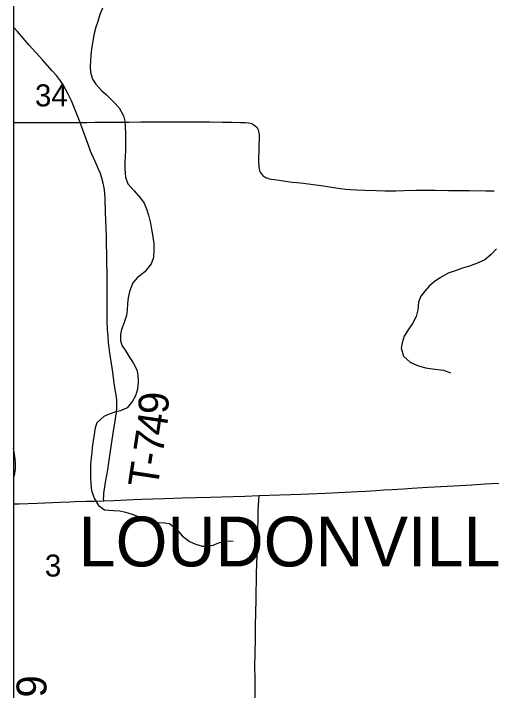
# Model space of a CAD drawing. Extents: x -7.5 to 53.5, y 0 to 22.
# Drawn here: x 2.1 to 3.008, y 16.532 to 17.82 of the extents above; entities that cross this region are included whole.
import ezdxf

# ---------------------------------------------------------------- set-up
doc = ezdxf.new("R2010")
doc.units = 0
for name, color, linetype in [('GM_X_Corporation', 7, 'Continuous'), ('GM_X_Corporation_Text', 7, 'Continuous'), ('GM_X_County_Road', 7, 'Continuous'), ('GM_X_Minor_River', 7, 'Continuous'), ('GM_X_Section_Text', 7, 'Continuous'), ('GM_X_Township_Road', 7, 'Continuous'), ('GM_X_Township_Road_Text', 7, 'Continuous'), ('SH_Data', 7, 'Continuous')]:
    doc.layers.add(name, color=color, linetype=linetype)

msp = doc.modelspace()

# ---------------------------------------------------------------- linework, layer by layer
at = {"layer": 'GM_X_Corporation'}
msp.add_lwpolyline([(4.6087, 14.5302), (4.6021, 15.6139), (4.594, 15.8096), (4.5873, 16.3533), (4.5872, 16.3635), (4.5826, 16.8462), (4.5822, 16.8992), (4.577, 17.1178), (4.5749, 17.2575), (4.5771, 17.6201), (4.5718, 18.1276), (4.5696, 18.2604), (4.5565, 19.1354), (5.0411, 19.1401), (6.0424, 19.1527), (6.0433, 19.1527), (6.5522, 19.1561), (7.544, 19.1455), (8.414, 19.1709), (8.5159, 19.1718), (8.9, 19.1887), (8.9, 20.9), (2.1, 20.9), (2.1, 14.1)], dxfattribs=at)
at = {"layer": 'GM_X_County_Road'}
for points in [[(2.5666, 16.9029), (2.6054, 16.9045), (2.6271, 16.9051), (2.6458, 16.9057), (2.6613, 16.9062), (2.6924, 16.9076), (2.7172, 16.9089), (2.7296, 16.9094), (2.7544, 16.9109), (2.7699, 16.9117), (2.7792, 16.9123), (2.7885, 16.9129), (2.804, 16.9139), (2.8195, 16.9149), (2.8413, 16.9162), (2.8568, 16.9172), (2.8878, 16.9189), (2.925, 16.921), (2.9714, 16.9238), (2.9962, 16.9253), (3.0085, 16.9259), (3.0302, 16.9268), (3.0605, 16.9283)], [(2.2713, 16.8933), (2.2909, 16.8939), (2.3281, 16.8956), (2.3436, 16.8962), (2.3871, 16.8977), (2.4213, 16.8985), (2.4462, 16.8991), (2.4741, 16.8998), (2.5176, 16.9013), (2.5394, 16.9022), (2.5666, 16.9029)], [(2.1, 16.8871), (2.1109, 16.8876), (2.145, 16.8889), (2.1885, 16.8905), (2.2071, 16.8913), (2.2164, 16.8916), (2.2381, 16.8922), (2.2537, 16.8927), (2.2713, 16.8933)]]:
    msp.add_lwpolyline(points, dxfattribs=at)
at = {"layer": 'GM_X_Minor_River'}
for points in [[(2.2688, 17.8302), (2.2642, 17.8184), (2.2604, 17.8051), (2.2566, 17.7945), (2.2528, 17.7797), (2.2509, 17.7679), (2.2486, 17.7569), (2.2466, 17.7417), (2.2463, 17.7303), (2.2459, 17.7193), (2.2462, 17.7087), (2.25, 17.6954), (2.2561, 17.6859), (2.2671, 17.6738), (2.2765, 17.6654), (2.2906, 17.6517), (2.3008, 17.6411), (2.3088, 17.6255), (2.3114, 17.6153), (2.3122, 17.6054), (2.3125, 17.591), (2.3125, 17.5594), (2.3117, 17.5366), (2.3117, 17.5249), (2.3128, 17.5086), (2.3173, 17.496), (2.3291, 17.4831), (2.3412, 17.469), (2.3484, 17.4592), (2.3534, 17.447), (2.3568, 17.4368), (2.3602, 17.4216), (2.3624, 17.4102), (2.3639, 17.3992), (2.3669, 17.3828), (2.3669, 17.3714), (2.3658, 17.3559), (2.3616, 17.3437), (2.3494, 17.3289), (2.335, 17.3175), (2.327, 17.308), (2.3202, 17.2913), (2.3179, 17.2792), (2.3167, 17.2686), (2.3159, 17.2556), (2.3144, 17.2454), (2.3098, 17.2306), (2.3053, 17.2188), (2.303, 17.2093), (2.3033, 17.1976), (2.3064, 17.1877), (2.3132, 17.1778), (2.3211, 17.1649), (2.3276, 17.1554)], [(3.0179, 17.3723), (3.008, 17.362), (2.9959, 17.3514), (2.9833, 17.3457), (2.967, 17.3393), (2.9537, 17.3358), (2.9397, 17.3309), (2.926, 17.326), (2.9097, 17.3169), (2.8994, 17.3097), (2.8899, 17.3017), (2.8815, 17.2922), (2.8743, 17.2827), (2.8698, 17.2713), (2.8682, 17.2565), (2.8652, 17.2436), (2.8583, 17.2303), (2.8503, 17.2186), (2.8424, 17.2064), (2.8389, 17.1939), (2.8366, 17.1833), (2.8412, 17.1684), (2.8541, 17.1567), (2.8677, 17.1506), (2.8833, 17.146), (2.8966, 17.1445), (2.9171, 17.1414), (2.9303, 17.1369)], [(2.3276, 17.1554), (2.3344, 17.1425), (2.3363, 17.1326), (2.3367, 17.1197), (2.3359, 17.1053), (2.3321, 17.0931), (2.326, 17.0829), (2.3157, 17.0703), (2.3032, 17.0643), (2.2926, 17.062), (2.2819, 17.0582), (2.2717, 17.0537), (2.258, 17.0415), (2.2549, 17.032), (2.2511, 17.007), (2.2492, 16.9948), (2.2488, 16.9853), (2.2473, 16.9751), (2.2465, 16.9622), (2.2461, 16.9489), (2.2465, 16.9386), (2.2472, 16.9249), (2.2484, 16.9128), (2.2533, 16.898), (2.2616, 16.8843), (2.273, 16.8759), (2.2897, 16.8744), (2.3018, 16.874), (2.3125, 16.8714), (2.3254, 16.8679), (2.3371, 16.8634), (2.3504, 16.8584), (2.361, 16.8543), (2.3747, 16.852), (2.3868, 16.8512), (2.3967, 16.8501), (2.4104, 16.8387), (2.4206, 16.8265), (2.4342, 16.8155), (2.4449, 16.8113), (2.4585, 16.8071), (2.4684, 16.8067), (2.4794, 16.809), (2.4916, 16.8136), (2.5045, 16.8166), (2.5174, 16.817)], [(2.1, 16.9396), (2.1015, 16.9413), (2.1034, 16.9542), (2.1038, 16.9656), (2.1027, 16.9774), (2.1008, 16.9892), (2.1, 16.9933)]]:
    msp.add_lwpolyline(points, dxfattribs=at)
at = {"layer": 'GM_X_Township_Road'}
for points in [[(2.2265, 17.6131), (2.2218, 17.6254), (2.2099, 17.6541), (2.2033, 17.6682), (2.1989, 17.6764), (2.1943, 17.6845), (2.1893, 17.6923), (2.1857, 17.6973), (2.1817, 17.7021), (2.1735, 17.7114), (2.1549, 17.7324), (2.13, 17.7602), (2.1075, 17.7859), (2.1, 17.7946)], [(2.1, 17.6127), (2.1006, 17.6128), (2.1221, 17.6131), (2.1436, 17.6132), (2.159, 17.6131), (2.1745, 17.6131), (2.1931, 17.6131), (2.2265, 17.6131)], [(2.2265, 17.6131), (2.2331, 17.6131), (2.2393, 17.6131), (2.2548, 17.6134), (2.2983, 17.6136), (2.32, 17.6137), (2.3418, 17.6139), (2.3542, 17.6141), (2.3759, 17.6143), (2.3977, 17.6143), (2.4287, 17.6143), (2.4504, 17.6142), (2.4722, 17.6139), (2.497, 17.6135), (2.5157, 17.6135), (2.5312, 17.6131), (2.5405, 17.6129), (2.5466, 17.6123), (2.5495, 17.6116), (2.5524, 17.6108), (2.5551, 17.6096), (2.5576, 17.608), (2.5599, 17.6062), (2.5618, 17.6039), (2.5635, 17.6015), (2.5648, 17.5989), (2.5658, 17.596), (2.5664, 17.593), (2.5666, 17.5901), (2.5667, 17.5867), (2.5667, 17.5833), (2.5665, 17.5676), (2.5657, 17.5371), (2.566, 17.5313), (2.566, 17.5281), (2.5666, 17.5248), (2.5675, 17.5211), (2.5688, 17.5187), (2.5704, 17.5159), (2.5724, 17.5133), (2.5748, 17.5111), (2.5775, 17.5093), (2.5804, 17.5079), (2.5834, 17.5068), (2.5865, 17.506), (2.5895, 17.5053), (2.5957, 17.5042), (2.605, 17.5031), (2.6172, 17.5012), (2.621, 17.5007)], [(2.2921, 17.1128), (2.2879, 17.1421), (2.2845, 17.1667), (2.2827, 17.1791), (2.2807, 17.1942), (2.2797, 17.2061), (2.2785, 17.2183), (2.2779, 17.237), (2.278, 17.2526), (2.278, 17.265), (2.2781, 17.2774), (2.2781, 17.2929), (2.2779, 17.3241), (2.2776, 17.3489), (2.2765, 17.3955), (2.2751, 17.442), (2.2741, 17.4669), (2.2732, 17.4793), (2.272, 17.4886), (2.2704, 17.4977), (2.2681, 17.5068), (2.265, 17.5156), (2.2615, 17.5242), (2.2577, 17.5328), (2.2526, 17.5441), (2.2465, 17.5583), (2.2409, 17.5728), (2.2346, 17.5903), (2.2274, 17.6109), (2.2265, 17.6131)], [(2.621, 17.5007), (2.6296, 17.4996), (2.6388, 17.4986), (2.6512, 17.4974), (2.6696, 17.4951), (2.685, 17.4931), (2.7126, 17.4888), (2.7218, 17.4874), (2.7311, 17.4863), (2.7404, 17.4854), (2.7528, 17.4846), (2.7683, 17.484), (2.79, 17.4835), (2.8055, 17.483), (2.8148, 17.4829), (2.8272, 17.483), (2.8428, 17.4833), (2.8645, 17.4839), (2.8769, 17.4841), (2.9017, 17.4839), (2.9266, 17.4835), (2.9514, 17.4835), (2.9669, 17.4835), (2.998, 17.4832), (3.0135, 17.483)], [(2.2713, 16.8933), (2.2712, 16.8972), (2.2713, 16.9012), (2.2715, 16.9047), (2.2719, 16.9079), (2.2735, 16.9199), (2.2755, 16.9316), (2.279, 16.9523), (2.2809, 16.9658), (2.2857, 16.9964), (2.2908, 17.0301), (2.2938, 17.0484), (2.2947, 17.0546), (2.2956, 17.0607), (2.2965, 17.0699), (2.2966, 17.0761), (2.2961, 17.0854), (2.2951, 17.0946), (2.2945, 17.0981), (2.2921, 17.1128)], [(2.5593, 16.4987), (2.5595, 16.5091), (2.5593, 16.5308), (2.559, 16.5557), (2.5589, 16.5775), (2.5592, 16.6024), (2.5596, 16.6304), (2.5599, 16.6553), (2.5609, 16.7051), (2.5613, 16.7237), (2.5616, 16.7362), (2.562, 16.7547), (2.5626, 16.7733), (2.5632, 16.7888), (2.5638, 16.8043), (2.5642, 16.823), (2.5644, 16.8386), (2.5648, 16.8603), (2.5652, 16.8727), (2.5657, 16.8851), (2.5666, 16.9029)]]:
    msp.add_lwpolyline(points, dxfattribs=at)
at = {"layer": 'SH_Data'}
msp.add_line((2.1, 20.9), (2.1, 14.1), dxfattribs=at)

# ---------------------------------------------------------------- texts
at = {"layer": 'GM_X_Corporation_Text'}
msp.add_text('LOUDONVILLE', height=0.094697, rotation=0, dxfattribs=at).set_placement((2.2236, 16.7683))
at = {"layer": 'GM_X_Section_Text'}
for s, height, p in [('34', 0.04186, (2.1407, 17.6436)), ('3', 0.0419, (2.1595, 16.749))]:
    msp.add_text(s, height=height, rotation=0, dxfattribs=at).set_placement(p)
at = {"layer": 'GM_X_Township_Road_Text'}
for s, height, rotation, p in [('9', 0.0568, 89.8094, (2.3946, 17.0582)), ('4', 0.0568, 81.5111, (2.3888, 17.015)), ('7', 0.0568, 81.1412, (2.3834, 16.9803)), ('-', 0.0568, 81.2198, (2.3798, 16.9574)), ('T', 0.0568, 81.3532, (2.3735, 16.9155)), ('T-759', 0.05682, 90, (2.1625, 16.3626))]:
    msp.add_text(s, height=height, rotation=rotation, dxfattribs=at).set_placement(p)

doc.saveas('drawing.dxf')
